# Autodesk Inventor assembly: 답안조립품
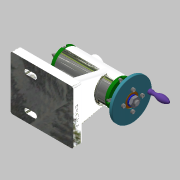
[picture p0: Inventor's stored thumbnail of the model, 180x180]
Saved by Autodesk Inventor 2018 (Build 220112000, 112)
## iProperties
Created: 2022-06
Part Number: 답안조립품
Material: 일반
Document SubType Name: Assembly
Designer: home
Author: home
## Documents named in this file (18)
- C:\Users\kimgi\Desktop\720606V1021\답안조립품.iam
- C:\Users\kimgi\Desktop\720606V1021\본체.ipt
- C:\Users\kimgi\Desktop\720606V1021\커버.ipt
- C:\Users\kimgi\Desktop\720606V1021\부시.ipt
- C:\Users\kimgi\Desktop\720606V1021\나사축.ipt
- C:\Users\kimgi\Desktop\720606V1021\플랜지.ipt
- C:\Users\kimgi\Desktop\720606V1021\키 4 x 4 x 10.ipt
- C:\Users\kimgi\Desktop\720606V1021\와셔.ipt
- C:\Users\kimgi\Desktop\720606V1021\너트 M8.ipt
- C:\Users\kimgi\Desktop\720606V1021\돌림판.ipt
- C:\Users\kimgi\Desktop\720606V1021\볼트 M3.ipt
- C:\Users\kimgi\Desktop\720606V1021\슬리브.ipt
- C:\Users\kimgi\Desktop\720606V1021\센터홀더.ipt
- C:\Users\kimgi\Desktop\720606V1021\중공축.ipt
- C:\Users\kimgi\Desktop\720606V1021\멈춤나사 M3.ipt
- C:\Users\kimgi\Desktop\720606V1021\센터.ipt
- C:\Users\kimgi\Desktop\720606V1021\나사.ipt
- C:\Users\kimgi\Desktop\720606V1021\핸들.ipt
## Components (2 placed, 2 different names)
1. 플랜지:1
2. 핸들:1
